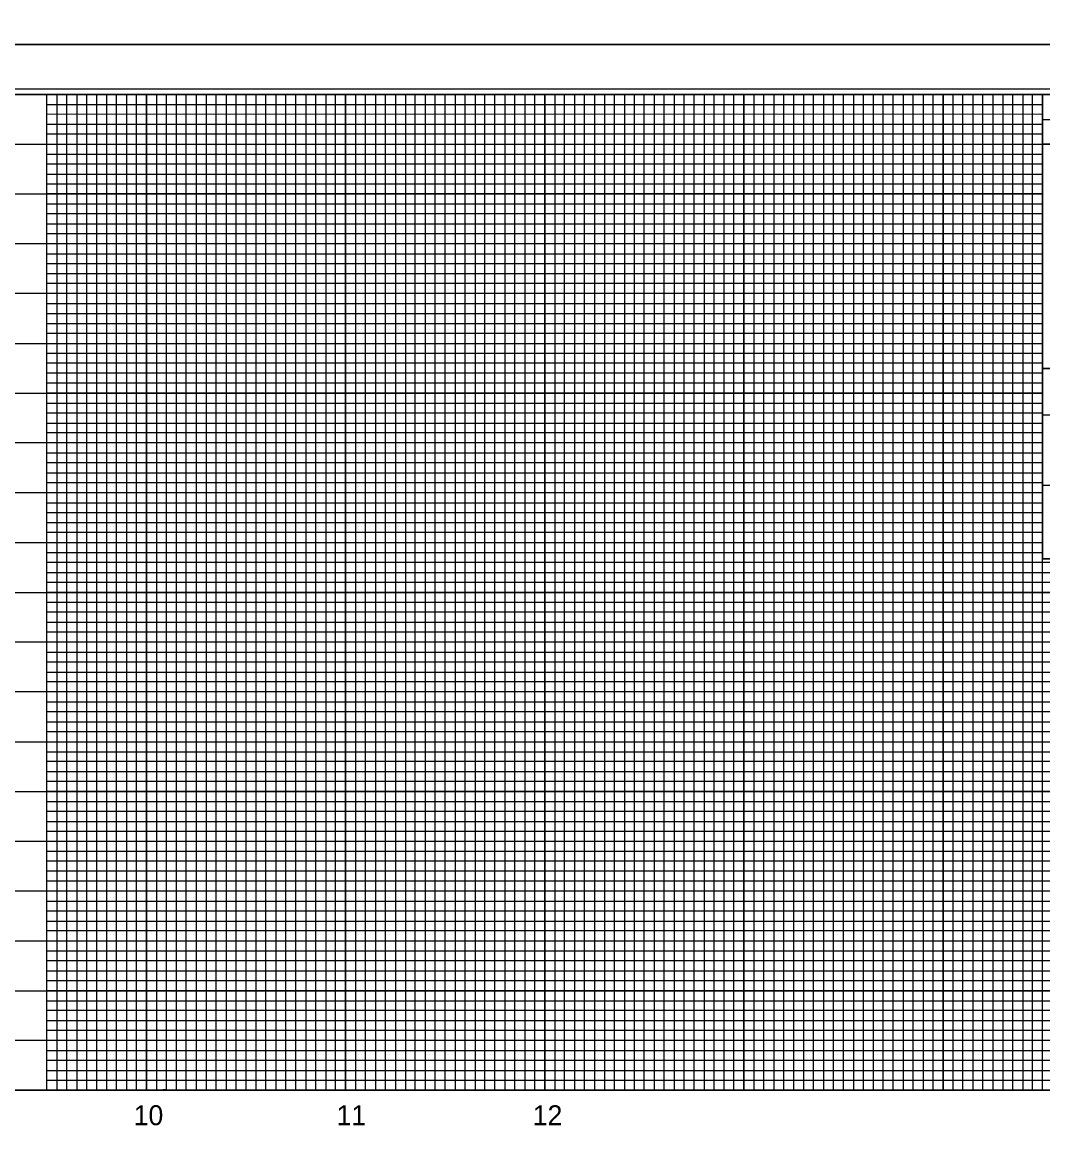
# Model space of a CAD drawing. Extents: x 1754992 to 1757273, y 732111 to 735411.
# Drawn here: x 1756135 to 1756648, y 732664 to 733222 of the extents above; entities that cross this region are included whole.
import ezdxf

# ---------------------------------------------------------------- set-up
doc = ezdxf.new("R2010")
doc.units = 0
for name, color, linetype in [('Old_Level_42', 7, 'Continuous'), ('Old_Level_43', 7, 'Continuous'), ('Scratch_Level_3', 7, 'Continuous'), ('Sheet Cutting Line CELL', 7, 'Continuous'), ('Sheet DOT Grid CELL', 7, 'Continuous'), ('Sheet Plot Border Inside CELL', 7, 'Continuous'), ('Sheet Plot Border Outside CELL', 7, 'Continuous'), ('Sheet Profile CELL', 7, 'Continuous'), ('Sheet Profile Grid Major CELL', 7, 'Continuous'), ('Sheet Profile Grid Middle CELL', 7, 'Continuous'), ('Sheet Profile Grid Minor CELL', 7, 'Continuous'), ('Sheet Sticker Exception Certification CELL', 7, 'Continuous')]:
    doc.layers.add(name, color=color, linetype=linetype)

msp = doc.modelspace()

# ---------------------------------------------------------------- linework, layer by layer
at = {"layer": 'Old_Level_42'}
msp.add_line((1756647.62, 733024.73), (1756647.62, 733048.23), dxfattribs=at)
msp.add_lwpolyline([(1756847.67, 732989.43), (1756647.62, 732989.43), (1756647.62, 733024.73)], dxfattribs=at)
at = {"layer": 'Old_Level_43'}
msp.add_lwpolyline([(1756847.68, 732952.66), (1756647.63, 732952.66), (1756647.63, 732989.43)], dxfattribs=at)
at = {"layer": 'Scratch_Level_3'}
msp.add_lwpolyline([(1755397.67, 732685.78), (1755397.67, 733185.78), (1756647.62, 733185.78), (1756647.63, 732952.66), (1756797.67, 732952.66), (1756797.67, 732685.78)], close=True, dxfattribs=at)
at = {"layer": 'Sheet Cutting Line CELL'}
for p, q in [((1756864.67, 733210.78), (1755180.67, 733210.78)), ((1755180.67, 733210.78), (1756864.67, 733210.78))]:
    msp.add_line(p, q, dxfattribs=at)
at = {"layer": 'Sheet DOT Grid CELL'}
for p, q in [((1756147.67, 732685.78), (1756147.67, 733185.78)), ((1756197.67, 732685.78), (1756197.67, 733185.78)), ((1756247.67, 732685.78), (1756247.67, 733185.78)), ((1756297.67, 732685.78), (1756297.67, 733185.78)), ((1756347.67, 732685.78), (1756347.67, 733185.78)), ((1756397.67, 732685.78), (1756397.67, 733185.78)), ((1756447.67, 732685.78), (1756447.67, 733185.78)), ((1756497.67, 732685.78), (1756497.67, 733185.78)), ((1756547.67, 732685.78), (1756547.67, 733185.78)), ((1756597.67, 732685.78), (1756597.67, 733185.78)), ((1756647.62, 733135.78), (1756147.67, 733135.78)), ((1756647.62, 733085.78), (1756147.67, 733085.78)), ((1756647.67, 732685.78), (1756647.67, 733048.23)), ((1756647.67, 733035.78), (1756147.67, 733035.78)), ((1756647.63, 732985.78), (1756147.67, 732985.78)), ((1756847.67, 732935.78), (1756147.67, 732935.78)), ((1756847.67, 732885.78), (1756147.67, 732885.78)), ((1756847.67, 732835.78), (1756147.67, 732835.78)), ((1756847.67, 732785.78), (1756147.67, 732785.78)), ((1756847.67, 732735.78), (1756147.67, 732735.78))]:
    msp.add_line(p, q, dxfattribs=at)
at = {"layer": 'Sheet Plot Border Inside CELL'}
msp.add_lwpolyline([(1755193.67, 732133.23), (1756860.17, 732133.23), (1756860.17, 733188.33), (1755193.67, 733188.33)], close=True, dxfattribs=at)
at = {"layer": 'Sheet Plot Border Outside CELL'}
for points in [[(1755180.67, 733210.78), (1756864.67, 733210.78), (1756864.67, 734310.78), (1755180.67, 734310.78)], [(1755180.67, 732110.78), (1756864.67, 732110.78), (1756864.67, 733210.78), (1755180.67, 733210.78)]]:
    msp.add_lwpolyline(points, close=True, dxfattribs=at)
at = {"layer": 'Sheet Profile CELL'}
for p, q in [((1756647.62, 733173.23), (1756847.67, 733173.23)), ((1755347.67, 732685.78), (1756847.67, 732685.78))]:
    msp.add_line(p, q, dxfattribs=at)
for points in [[(1756847.67, 733185.78), (1755347.67, 733185.78), (1755347.67, 732135.78), (1756847.67, 732135.78)], [(1756647.62, 733185.78), (1756847.67, 733185.78), (1756847.67, 733160.73), (1756647.62, 733160.73)], [(1756647.62, 733160.73), (1756747.67, 733160.73), (1756747.67, 733048.23), (1756647.62, 733048.23)]]:
    msp.add_lwpolyline(points, close=True, dxfattribs=at)
at = {"layer": 'Sheet Profile Grid Major CELL'}
for points in [[(1756097.67, 732685.78), (1756147.67, 732685.78), (1756147.67, 733185.78), (1756197.67, 733185.78), (1756197.67, 732685.78), (1756247.67, 732685.78), (1756247.67, 733185.78), (1756297.67, 733185.78), (1756297.67, 732685.78), (1756347.67, 732685.78), (1756347.67, 733185.78), (1756397.67, 733185.78), (1756397.67, 732685.78), (1756447.67, 732685.78), (1756447.67, 733185.78), (1756497.67, 733185.78), (1756497.67, 732685.78), (1756547.67, 732685.78), (1756547.67, 733185.78), (1756597.67, 733185.78), (1756597.67, 732685.78), (1756647.67, 732685.78), (1756647.67, 733185.78), (1756673.97, 733185.78)], [(1755347.67, 733135.78), (1756647.67, 733135.78)], [(1756647.67, 733085.78), (1755347.67, 733085.78), (1755347.67, 733035.78), (1756647.67, 733035.78)], [(1756647.63, 732985.78), (1755347.67, 732985.78), (1755347.67, 732935.78), (1756847.67, 732935.78)], [(1756847.67, 732885.78), (1755347.67, 732885.78), (1755347.67, 732835.78), (1756847.67, 732835.78)], [(1756847.67, 732785.78), (1755347.67, 732785.78), (1755347.67, 732785.78), (1755347.67, 732735.78), (1756847.67, 732735.78)]]:
    msp.add_lwpolyline(points, dxfattribs=at)
at = {"layer": 'Sheet Profile Grid Middle CELL'}
for p, q in [((1756172.67, 732685.78), (1756172.67, 733185.78)), ((1756172.67, 733185.78), (1756222.67, 733185.78)), ((1756222.67, 733185.78), (1756222.67, 732685.78)), ((1756272.67, 732685.78), (1756272.67, 733185.78)), ((1756272.67, 733185.78), (1756322.67, 733185.78)), ((1756322.67, 733185.78), (1756322.67, 732685.78)), ((1756372.67, 732685.78), (1756372.67, 733185.78)), ((1756372.67, 733185.78), (1756422.67, 733185.78)), ((1756422.67, 733185.78), (1756422.67, 732685.78)), ((1756472.67, 732685.78), (1756472.67, 733185.78)), ((1756472.67, 733185.78), (1756522.67, 733185.78)), ((1756522.67, 733185.78), (1756522.67, 732685.78)), ((1756572.67, 732685.78), (1756572.67, 733185.78)), ((1756572.67, 733185.78), (1756622.67, 733185.78)), ((1756622.67, 733185.78), (1756622.67, 732685.78)), ((1755347.67, 733160.78), (1756647.62, 733160.78)), ((1756122.67, 732685.78), (1756172.67, 732685.78)), ((1756222.67, 732685.78), (1756272.67, 732685.78)), ((1756322.67, 732685.78), (1756372.67, 732685.78)), ((1756422.67, 732685.78), (1756472.67, 732685.78)), ((1756522.67, 732685.78), (1756572.67, 732685.78)), ((1756622.67, 732685.78), (1756672.67, 732685.78))]:
    msp.add_line(p, q, dxfattribs=at)
for points in [[(1756647.67, 733110.78), (1755347.67, 733110.78), (1755347.67, 733060.78), (1756647.67, 733060.78)], [(1756647.62, 733010.78), (1755347.67, 733010.78), (1755347.67, 732960.78), (1756647.63, 732960.78)], [(1756847.67, 732910.78), (1755347.67, 732910.78), (1755347.67, 732860.78), (1756847.67, 732860.78)], [(1756847.67, 732810.78), (1755347.67, 732810.78), (1755347.67, 732760.78), (1756847.67, 732760.78)], [(1756847.67, 732710.78), (1755347.67, 732710.78)]]:
    msp.add_lwpolyline(points, dxfattribs=at)
at = {"layer": 'Sheet Profile Grid Minor CELL'}
for p, q in [((1756132.67, 733185.78), (1756137.67, 733185.78)), ((1756142.67, 733185.78), (1756152.67, 733185.78)), ((1756152.67, 733185.78), (1756152.67, 732685.78)), ((1756157.67, 732685.78), (1756157.67, 733185.78)), ((1756157.67, 733185.78), (1756162.67, 733185.78)), ((1756162.67, 733185.78), (1756162.67, 732685.78)), ((1756167.67, 732685.78), (1756167.67, 733185.78)), ((1756167.67, 733185.78), (1756177.67, 733185.78)), ((1756177.67, 733185.78), (1756177.67, 732685.78)), ((1756182.67, 732685.78), (1756182.67, 733185.78)), ((1756182.67, 733185.78), (1756187.67, 733185.78)), ((1756187.67, 733185.78), (1756187.67, 732685.78)), ((1756192.67, 732685.78), (1756192.67, 733185.78)), ((1756192.67, 733185.78), (1756202.67, 733185.78)), ((1756202.67, 733185.78), (1756202.67, 732685.78)), ((1756207.67, 732685.78), (1756207.67, 733185.78)), ((1756207.67, 733185.78), (1756212.67, 733185.78)), ((1756212.67, 733185.78), (1756212.67, 732685.78)), ((1756217.67, 732685.78), (1756217.67, 733185.78)), ((1756217.67, 733185.78), (1756227.67, 733185.78)), ((1756227.67, 733185.78), (1756227.67, 732685.78)), ((1756147.67, 733180.78), (1756647.67, 733180.78)), ((1756647.67, 733175.78), (1756147.67, 733175.64)), ((1756147.67, 733170.78), (1756647.67, 733170.78)), ((1756647.62, 733050.78), (1756147.67, 733050.78)), ((1756647.67, 733045.78), (1756147.67, 733045.78)), ((1756647.67, 733040.78), (1756147.67, 733040.78)), ((1756147.67, 733030.78), (1756647.67, 733030.78)), ((1756647.67, 733025.78), (1756147.67, 733025.78)), ((1756147.67, 733020.78), (1756647.62, 733020.78)), ((1756647.62, 733000.78), (1756147.67, 733000.78)), ((1756147.67, 732995.78), (1756647.62, 732995.78)), ((1756647.63, 732975.78), (1756147.67, 732975.78)), ((1756147.67, 732970.78), (1756647.63, 732970.78)), ((1756797.67, 732950.78), (1756147.67, 732950.78)), ((1756147.67, 732945.78), (1756797.67, 732945.78)), ((1756797.67, 732940.78), (1756147.67, 732940.78)), ((1756147.67, 732930.78), (1756797.67, 732930.78)), ((1756797.67, 732925.78), (1756147.67, 732925.78)), ((1756147.67, 732920.78), (1756797.67, 732920.78)), ((1756797.67, 732915.78), (1756147.67, 732915.78)), ((1756147.67, 732905.78), (1756797.67, 732905.78)), ((1756797.67, 732900.78), (1756147.67, 732900.78)), ((1756147.67, 732895.78), (1756797.67, 732895.78)), ((1756797.67, 732890.78), (1756147.67, 732890.78)), ((1756147.67, 732880.78), (1756797.67, 732880.78)), ((1756797.67, 732875.78), (1756147.67, 732875.78)), ((1756147.67, 732870.78), (1756797.67, 732870.78)), ((1756797.67, 732865.78), (1756147.67, 732865.78)), ((1756147.67, 732855.78), (1756797.67, 732855.78)), ((1756797.67, 732850.78), (1756147.67, 732850.78)), ((1756147.67, 732845.78), (1756797.67, 732845.78)), ((1756797.67, 732840.78), (1756147.67, 732840.78)), ((1756147.67, 732830.78), (1756797.67, 732830.78)), ((1756797.67, 732825.78), (1756147.67, 732825.78)), ((1756147.67, 732820.78), (1756797.67, 732820.78)), ((1756797.67, 732815.78), (1756147.67, 732815.78)), ((1756147.67, 732805.78), (1756797.67, 732805.78)), ((1756797.67, 732800.78), (1756147.67, 732800.78)), ((1756797.67, 732795.78), (1756147.67, 732795.78)), ((1756797.67, 732790.78), (1756147.67, 732790.78)), ((1756147.67, 732780.78), (1756797.67, 732780.78)), ((1756797.67, 732775.78), (1756147.67, 732775.78)), ((1756147.67, 732770.78), (1756797.67, 732770.78)), ((1756797.67, 732765.78), (1756147.67, 732765.78)), ((1756147.67, 732755.78), (1756797.67, 732755.78)), ((1756797.67, 732750.78), (1756147.67, 732750.78)), ((1756147.67, 732745.78), (1756797.67, 732745.78)), ((1756797.67, 732740.78), (1756147.67, 732740.78)), ((1756147.67, 732730.78), (1756797.67, 732730.78)), ((1756797.67, 732725.78), (1756147.67, 732725.78)), ((1756147.67, 732720.78), (1756797.67, 732720.78)), ((1756797.67, 732715.78), (1756147.67, 732715.78)), ((1756147.67, 732705.78), (1756797.67, 732705.78)), ((1756797.67, 732700.78), (1756147.67, 732700.78)), ((1756147.67, 732695.78), (1756797.67, 732695.78)), ((1756137.67, 732685.78), (1756142.67, 732685.78)), ((1756152.67, 732685.78), (1756157.67, 732685.78)), ((1756162.67, 732685.78), (1756167.67, 732685.78)), ((1756177.67, 732685.78), (1756182.67, 732685.78)), ((1756187.67, 732685.78), (1756192.67, 732685.78)), ((1756202.67, 732685.78), (1756207.37, 732686.33)), ((1756207.37, 732686.33), (1756207.67, 732685.78)), ((1756212.67, 732685.78), (1756217.67, 732685.78)), ((1756227.67, 732685.78), (1756232.67, 732685.78))]:
    msp.add_line(p, q, dxfattribs=at)
for points in [[(1756232.67, 732685.78), (1756232.67, 733185.78), (1756237.67, 733185.78), (1756237.67, 732685.78), (1756242.67, 732685.78), (1756242.67, 733185.78), (1756252.67, 733185.78), (1756252.67, 732685.78), (1756257.67, 732685.78), (1756257.67, 733185.78), (1756262.67, 733185.78), (1756262.67, 732685.78), (1756267.67, 732685.78), (1756267.67, 733185.78), (1756277.67, 733185.78), (1756277.67, 732685.78), (1756282.67, 732685.78), (1756282.67, 733185.78), (1756287.67, 733185.78), (1756287.67, 732685.78), (1756292.67, 732685.78), (1756292.67, 733185.78), (1756302.67, 733185.78), (1756302.67, 732685.78), (1756307.67, 732685.78), (1756307.67, 733185.78), (1756312.67, 733185.78), (1756312.67, 732685.78), (1756317.67, 732685.78), (1756317.67, 733185.78), (1756327.67, 733185.78), (1756327.67, 732685.78), (1756332.67, 732685.78), (1756332.67, 733185.78), (1756337.67, 733185.78), (1756337.67, 732685.78), (1756342.67, 732685.78), (1756342.67, 733185.78), (1756352.67, 733185.78), (1756352.67, 732685.78), (1756357.67, 732685.78), (1756357.67, 733185.78), (1756362.67, 733185.78), (1756362.67, 732685.78), (1756367.67, 732685.78), (1756367.67, 733185.78), (1756377.67, 733185.78), (1756377.67, 732685.78), (1756382.67, 732685.78), (1756382.67, 733185.78), (1756387.67, 733185.78), (1756387.67, 732685.78), (1756392.67, 732685.78), (1756392.67, 733185.78), (1756402.67, 733185.78), (1756402.67, 732685.78), (1756407.67, 732685.78), (1756407.67, 733185.78), (1756412.67, 733185.78), (1756412.67, 732685.78), (1756417.67, 732685.78), (1756417.67, 733185.78), (1756427.67, 733185.78), (1756427.67, 732685.78), (1756432.67, 732685.78), (1756432.67, 733185.78), (1756437.67, 733185.78), (1756437.67, 732685.78), (1756442.67, 732685.78), (1756442.67, 733185.78), (1756452.67, 733185.78), (1756452.67, 732685.78), (1756457.67, 732685.78), (1756457.67, 733185.78), (1756462.67, 733185.78), (1756462.67, 732685.78), (1756467.67, 732685.78), (1756467.67, 733185.78), (1756477.67, 733185.78), (1756477.67, 732685.78), (1756482.67, 732685.78), (1756482.67, 733185.78), (1756487.67, 733185.78), (1756487.67, 732685.78), (1756492.67, 732685.78), (1756492.67, 733185.78), (1756502.67, 733185.78), (1756502.67, 732685.78), (1756507.67, 732685.78), (1756507.67, 733185.78), (1756512.67, 733185.78), (1756512.67, 732685.78), (1756517.67, 732685.78), (1756517.67, 733185.78), (1756527.67, 733185.78), (1756527.67, 732685.78), (1756532.67, 732685.78), (1756532.67, 733185.78), (1756537.67, 733185.78), (1756537.67, 732685.78)], [(1756537.67, 732685.78), (1756542.67, 732685.78), (1756542.67, 733185.78), (1756552.67, 733185.78), (1756552.67, 732685.78), (1756557.67, 732685.78), (1756557.67, 733185.78), (1756562.67, 733185.78), (1756562.67, 732685.78), (1756567.67, 732685.78), (1756567.67, 733185.78), (1756577.67, 733185.78), (1756577.67, 732685.78), (1756582.67, 732685.78), (1756582.67, 733185.78), (1756587.67, 733185.78), (1756587.67, 732685.78), (1756592.67, 732685.78), (1756592.67, 733185.78), (1756602.67, 733185.78), (1756602.67, 732685.78), (1756607.67, 732685.78), (1756607.67, 733185.78), (1756612.67, 733185.78), (1756612.67, 732685.78), (1756617.67, 732685.78), (1756617.67, 733185.78), (1756627.67, 733185.78), (1756627.67, 732685.78), (1756632.67, 732685.78), (1756632.67, 733185.78), (1756637.67, 733185.78), (1756637.67, 732685.78), (1756642.67, 732685.78), (1756642.67, 733185.78), (1756652.67, 733185.78)], [(1756647.67, 733165.78), (1756147.67, 733165.78)], [(1756147.67, 733155.78), (1756647.67, 733155.78)], [(1756647.62, 733150.78), (1756147.67, 733150.78)], [(1756147.67, 733145.78), (1756647.67, 733145.78)], [(1756647.67, 733140.78), (1756147.67, 733140.78)], [(1756147.67, 733130.78), (1756647.67, 733130.78)], [(1756647.67, 733125.78), (1756147.67, 733125.78)], [(1756147.67, 733120.78), (1756647.67, 733120.78)], [(1756647.67, 733115.78), (1756147.67, 733115.78)], [(1756147.67, 733105.78), (1756647.67, 733105.78)], [(1756647.67, 733100.78), (1756147.67, 733100.78)], [(1756147.67, 733095.78), (1756647.67, 733095.78)], [(1756647.67, 733090.78), (1756147.67, 733090.78)], [(1756147.67, 733080.78), (1756647.67, 733080.78)], [(1756647.67, 733075.68), (1756147.67, 733075.68)], [(1756147.67, 733070.78), (1756647.67, 733070.78)], [(1756647.67, 733065.78), (1756147.67, 733065.78)], [(1756147.67, 733055.78), (1756647.67, 733055.78)], [(1756647.62, 733015.78), (1756147.67, 733015.78)], [(1756147.67, 733005.78), (1756647.62, 733005.78)], [(1756647.62, 732990.78), (1756147.67, 732990.78)], [(1756147.67, 732980.78), (1756647.63, 732980.78)], [(1756647.63, 732965.78), (1756147.67, 732965.78)], [(1756147.67, 732955.78), (1756647.63, 732955.78)], [(1756797.67, 732690.78), (1756147.67, 732690.78)]]:
    msp.add_lwpolyline(points, dxfattribs=at)
at = {"layer": 'Sheet Sticker Exception Certification CELL'}
for p, q in [((1756647.62, 733024.73), (1756647.62, 733048.23)), ((1756647.62, 733048.23), (1756847.66, 733048.23)), ((1756647.62, 733024.73), (1756647.62, 733048.23)), ((1756647.62, 733048.23), (1756847.66, 733048.23)), ((1756847.66, 733024.73), (1756647.62, 733024.73)), ((1756847.66, 733024.73), (1756647.62, 733024.73))]:
    msp.add_line(p, q, dxfattribs=at)

# ---------------------------------------------------------------- texts
at = {"layer": 'Scratch_Level_3'}
for s, p in [('10', (1756191.25, 732668.28)), ('11', (1756293.09, 732668.28)), ('12', (1756391.64, 732668.28))]:
    msp.add_text(s, height=10, dxfattribs=at).set_placement(p)

doc.saveas('drawing.dxf')
